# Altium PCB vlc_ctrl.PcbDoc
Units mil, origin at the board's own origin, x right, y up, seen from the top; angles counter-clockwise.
Board outline 1075 x 600 mil, 2 copper layers (Top Layer, Bottom Layer); 22 components, 13 nets, 59 pads, 2 vias.
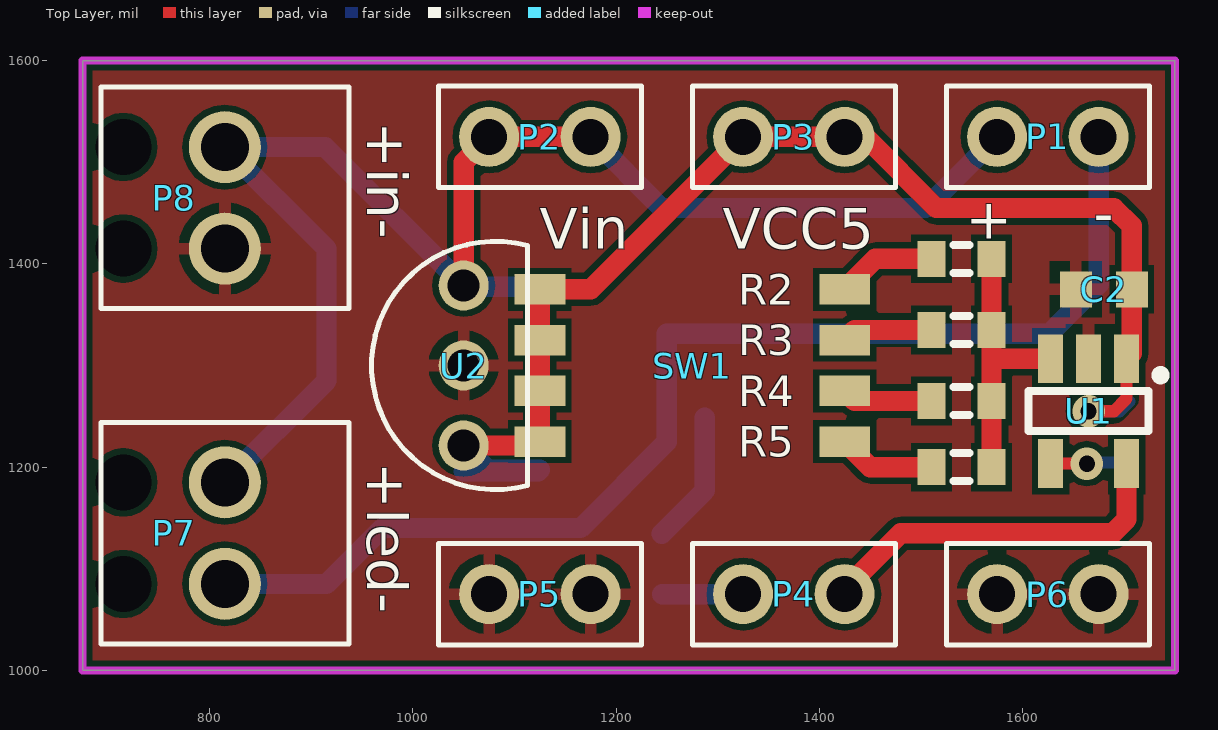
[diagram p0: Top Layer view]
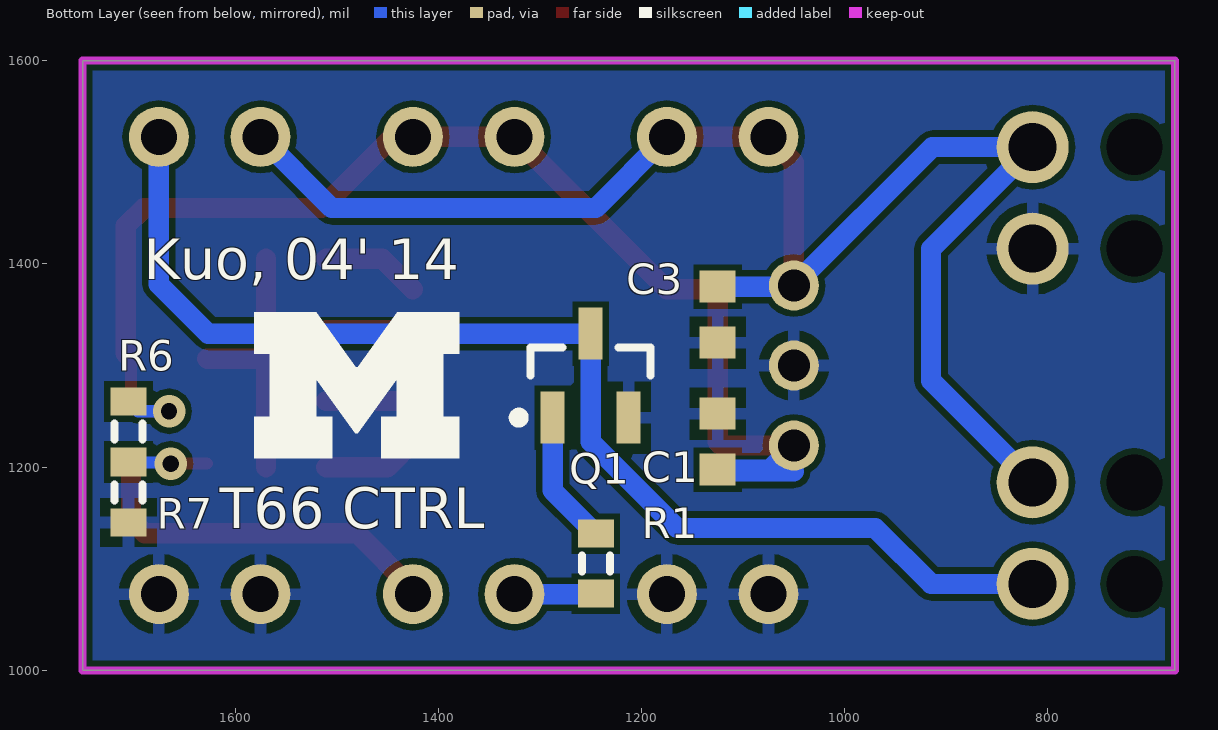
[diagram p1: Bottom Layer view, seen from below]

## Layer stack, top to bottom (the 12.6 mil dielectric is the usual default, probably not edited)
Top Solder: solder mask 0.4, Solder Resist, Dk 3.5
Top Layer: signal copper 1.4
Dielectric 1: dielectric 12.6, FR-4, Dk 4.8
Bottom Layer: signal copper 1.4
Bottom Solder: solder mask 0.4, Solder Resist, Dk 3.5

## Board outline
675,1000 675,1600 1750,1600 1750,1000

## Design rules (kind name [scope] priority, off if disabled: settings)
Clearance "Clearance~Sunstone Circuits" [All] p1: gap=6 // Sunstone Circuits Minimum Clearance Rule (Double Sided)
HoleSize "HoleSize~Sunstone Circuits" [All] p1: absolutevalues=TRUE maxlimit=251 minlimit=16 maxpercent=80.000 minpercent=20.000 // SSC Hole Size Rule For Single Sided & Double Sided Designs.
HoleSize Testpoint [All] p2: absolutevalues=TRUE maxlimit=100 minlimit=1 maxpercent=80.000 minpercent=20.000
HoleSize TestPointUsage [All] p3: absolutevalues=TRUE maxlimit=100 minlimit=1 maxpercent=80.000 minpercent=20.000
MinimumAnnularRing "MinimumAnnularRing~Sunstone Circuits" [All] p1: minimumring=7 // Sunstone Circuits Minimum Annular Ring (Double Sided)
PlaneClearance "PlaneClearance~Sunstone Circuits" [All] p1: clearance=12 // Sunstone Circuits Power Plane Clearance Rule (Double Sided)
PlaneConnect "PlaneConnect~Sunstone Circuits" [All] p1: planeconnectstyle=Relief reliefexpansion=10 reliefentries=4 reliefconductorwidth=8 reliefairgap=10 // Sunstone Circuits Power Plane Connect Rule (Double Sided)
PolygonConnect "PolygonConnect~Sunstone Circuits" [All] p1: connectstyle=Relief reliefconductorwidth=12 reliefentries=4 polygonreliefangle="90 Angle" airgapwidth=10 // Sunstone Circuits Polygon Connect Style (Double Sided)
RoomDefinition vlc_ctrl [InComponentClass('vlc_ctrl')] p1: confinementstyle=ConfineIn formatcopy=TRUE lockcomponents=FALSE outline 677.44,1013.44 677.44,1586.56 1012.5,1586.56 1012.5,1587.5 1737.5,1587.5 1737.5,1408.62 1739.21,1408.62 1739.21,1343.59 1754.8,1343.59 1754.8,1166.41 1737.5,1166.41 1737.5,1012.5 1012.5,1012.5 1012.5,1013.44
RoutingVias "RoutingVias~Sunstone Circuits" [All] p1: holewidth=16 width=30 viastyle="Through Hole" minholewidth=16 minwidth=30 maxholewidth=20 maxwidth=40 // Sunstone Circuits Routing Vias Rule (Double Sided)
ShortCircuit "ShortCircuit~Sunstone Circuits" [All] p1: allowed=FALSE // Sunstone Circuits Short Circuit Rule~Do Not Allow (Double Sided)
SolderMaskExpansion "SolderMaskExpansion~Sunstone Circuits" [All] p1: expansion=3 // Sunstone Circuits Solder Mask Expansion Rule (Double Sided)
ViasUnderSMD "ViasUnderSMD~Sunstone Circuits" [All] p1: allowed=FALSE // Sunstone Circuits Vias Under SMD~Do Not Allow (Double Sided)
Width "Width~Sunstone Circuits" [All] p1: maxlimit=100 minlimit=6 preferedwidth=10 // Sunstone Circuits Minimum Width Rule (Double Sided)
25 further rules are at their usual default settings.

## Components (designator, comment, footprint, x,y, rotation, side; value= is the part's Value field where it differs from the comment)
C1 "Cap Semi" 1608[0603] 1125,1225 r270 bottom
C2 "Cap Semi" 1608[0603] 1680,1375 r0 top
C3 "Cap Semi" 1608[0603] 1125,1350 r90 bottom
P1 "1 x 2 header" "1X2 HEADER" 1625,1525 r180 top
P2 "1 x 2 header" "1X2 HEADER" 1125,1525 r180 top
P3 "1 x 2 header" "1X2 HEADER" 1375,1525 r180 top
P4 "1 x 2 header" "1X2 HEADER" 1375,1075 r180 top
P5 "1 x 2 header" "1X2 HEADER" 1125,1075 r180 top
P6 "1 x 2 header" "1X2 HEADER" 1625,1075 r180 top
P7 "Screw connector" MPT_2POSITION 815,1135 r270 top
P8 "Screw connector" MPT_2POSITION 815,1465 r270 top
Q1 "Si2312CDS" SOT95P250-3N 1250,1290 r90 bottom
R1 "Res3" J1-0603 1245,1105 r270 bottom
R2 "Res3" J1-0603 1540,1405 r180 top
R3 "Res3" J1-0603 1540,1335 r180 top
R4 "Res3" J1-0603 1540,1265 r180 top
R5 "Res3" J1-0603 1540,1200 r180 top
R6 "Res3" J1-0603 1705,1235 r90 bottom
R7 "Res3" J1-0603 1705,1175 r270 bottom
SW1 "CHS-04TB" CHS04TB 1275,1300 r270 top
U1 "LTC6900" TSOT23 1665,1255 r180 top
U2 "LM78L05" TO92 1050,1300 r90 top

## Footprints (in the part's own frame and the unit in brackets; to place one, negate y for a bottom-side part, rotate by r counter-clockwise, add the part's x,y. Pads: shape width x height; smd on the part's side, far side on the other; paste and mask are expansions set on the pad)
"1X2 HEADER" [mm] "1x2 header, 100 mils"
  round 1.5 hole 0.9: 1(-1.27,0) 2(1.27,0)
  silkscreen extent -2.54,-1.27 2.54,1.27, body extent -2.53,-1.26 2.53,1.26, height 8.38
1608[0603] [mm] "Chip Capacitor, Body 1.6x0.8mm, IPC High Density"
  rect 0.8x0.9 smd: 1(-0.7,0) 2(0.7,0)
  body extent -0.87,-0.48 0.87,0.48, height 1.3
CHS04TB [mm] "4 POS DIP SWITCH"
  rect 0.76x1.27 smd: 1(-1.905,-3.81) 2(-1.905,3.81) 3(-0.635,-3.81) 4(-0.635,3.81) 5(0.635,-3.81) 6(0.635,3.81) 7(1.905,-3.81) 8(1.905,3.81)
J1-0603 [mm] "Chip Resistor, Body 1.6x0.8mm, IPC High Density"
  rect 0.7x0.9 smd: 1(-0.75,0) 2(0.75,0)
  silkscreen extent -0.2,-0.35 0.2,0.35, body extent -0.85,-0.48 0.85,0.48, height 0.9
MPT_2POSITION [mm] "Screw connector 2 pos"
  round 1.8 hole 1.2: 1(-1.27,0) 2(1.27,0)
  round 0 hole 1.4: ""(-1.27,-2.54) ""(1.27,-2.54)
  silkscreen extent -2.77,-3.1 2.77,3.1
SOT95P250-3N [mm] "SOT23, 3-Leads, Body 2.9x1.3mm, Pitch 0.95mm, Lead Span 2.3mm, IPC Medium Density"
  rect 1.3x0.6 smd: 1(-1.05,0.95) 2(-1.05,-0.95) 3(1.05,0)
  silkscreen extent -1.17,-1.5 0.7,1.93, body extent -0.7,-1.5 0.7,1.5, height 1.2
TO92 [mm]
  round 1.25 hole 0.8: 1(-2,0) 2(0,0) 3(2,0)
  silkscreen extent -3.1,-1.6 3.1,2.3
TSOT23 [mm]
  rect 0.62x1.22 smd: 1(-0.95,-1.31) 2(0,-1.31) 3(0.95,-1.31) 4(0.95,1.31) 5(-0.95,1.31)
  silkscreen extent -1.9,-1 1.5,0.5

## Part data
C1 C2 C3: "Capacitor (Semiconductor SIM Model)"
P1 P2 P3 P4 P5 P6: "100 mils standard header"
P7 P8: library part MPT_2POS, "Screw connector 2 positions"
Q1: "N-Channel 20 V (D-S) MOSFET"
R1 R2 R3 R4 R5 R6 R7: "Resistor"
SW1: "SLIDE SWITCHES"
U1: "Low Power, 1kHz to 20MHz   Resistor Set SOT-23 Oscillator"
U2: "LM78LXX Series 3-Terminal Positive Regulators"

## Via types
v1: diameter 32, hole 16, Top Layer to Bottom Layer, 2 vias

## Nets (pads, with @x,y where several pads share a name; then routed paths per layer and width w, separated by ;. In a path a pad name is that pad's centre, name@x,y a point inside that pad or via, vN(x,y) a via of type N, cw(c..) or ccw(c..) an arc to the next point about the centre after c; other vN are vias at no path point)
GND: C1.1 C2.1 C3.1 P5.1 P5.2 P6.1 P6.2 P8.2 Q1.2 R7.2 U1.2 U2.2
NetP1_1: P1.1 P7.2 Q1.3 | length 1189.5
  Bottom Layer w20: P7.2 915,1085 970,1140 1165,1140 1250,1225 Q1.3 1626.34,1331.34 1675,1380 P1.1
NetP4_1: P4.1 U1.5 | length 365.7
  Top Layer w20: P4.1 1425,1080 1480,1135 1688.83,1135 1702.4,1148.57 U1.5
NetP4_2: P4.2 R1.2 | length 79.5
  Bottom Layer w20: R1.2@1245.47,1075 P4.2
NetQ1_1: Q1.1 R1.1 | length 131.7
  Bottom Layer w20: R1.1 1287.4,1176.93 Q1.1
NetR2_1: R2.1 R3.1 R4.1 R5.1 U1.3 | length 261.5
  Top Layer w20: R5.1 R4.1 R3.1 R2.1 ; 1571.1,1306.57 U1.3
NetR2_2: R2.2 SW1.2 | length 97.9
  Top Layer w20: SW1.2 1455,1405 R2.2
NetR3_2: R3.2 SW1.4 | length 89.6
  Top Layer w20: SW1.4 1435,1335 R3.2
NetR4_2: R4.2 SW1.6 | length 89.6
  Top Layer w20: SW1.6 1435,1265 R4.2
NetR5_2: R5.2 SW1.8 | length 95.8
  Top Layer w20: SW1.8 1450,1200 R5.2
NetR6_1: R6.1 R7.1 U1.4 | length 77.9
  Top Layer w12: U1.4 v1(1663.43,1203.43)
  Bottom Layer w12: v1(1663.43,1203.43) 1664.53,1204.53 R7.1
VCC5: C1.2 C2.2 P3.1 P3.2 R6.2 SW1.1 SW1.3 SW1.5 SW1.7 U1.1 U2.1 | length 1324.3
  Top Layer w12: v1(1665,1255) 1690,1255 1702.4,1267.4 U1.1
  Top Layer w20: U2.1 1121.26,1221.26 SW1.7 SW1.5 SW1.3 SW1.1 1175,1375 P3.2 P3.1 1445,1525 1515,1455 1690,1455 1707.56,1437.44 C2.2 1707.56,1311.73 U1.1
  Bottom Layer w12: v1(1665,1255) 1695.47,1255 R6.2
  Bottom Layer w20: 1050,1195.67 C1.2@1123.23,1195.67 ; U2.1 1073.82,1197.44 C1.2
VIN: C3.2 P1.2 P2.1 P2.2 P7.1 P8.1 U2.3 | length 1494.4
  Top Layer w20: U2.3 1050,1500 P2.2 P2.1
  Bottom Layer w20: P7.1 915,1285 915,1415 P8.1 913.74,1515 U2.3 1051.18,1377.56 C3.2 ; P2.1 1245,1455 1505,1455 P1.2
pads on no net: P7. P8.

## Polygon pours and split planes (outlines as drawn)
GND on Top Layer "Bottom Layer-No Net" (solid, pour order 2): 675,1600 1750,1600 1750,1000 675,1000
GND on Bottom Layer "Bottom Layer-No Net" (solid, pour order 4): 675,1600 1750,1600 1750,1000 675,1000

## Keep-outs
Keep-Out Layer:
  the board outline again, w7.87

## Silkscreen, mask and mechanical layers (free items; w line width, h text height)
Top Overlay:
  text "+in-" at 955,1540 h40 r270
  text "-" at 1690,1430 h40
  text "+" at 1590,1425 h40
  text "Vin" at 1125,1415 h40
  text "VCC5" at 1305,1415 h40
  text "+led-" at 955,1205 h40 r270
Bottom Overlay:
  region: 1581.1,1208.63 1504.38,1208.63 1504.38,1249.6 1519.98,1249.6 1519.98,1286.66 1481.94,1233.34 1479.34,1233.34 1440.66,1286.66 1440.66,1249.6 1456.26,1249.6 1456.26,1208.63 1379.54,1208.63 1379.54,1249.6 1395.14,1249.6 1395.14,1311.37 1379.54,1311.37 1379.54,1352.33 1440.33,1352.33 1479.34,1298.36 1481.29,1298.36 1520.31,1352.33 1581.1,1352.33 1581.1,1311.37 1566.14,1311.37 1566.14,1249.6 1581.1,1249.6
  text "Kuo, 04' 14" at 1690,1385 h40
  text "T66 CTRL" at 1615,1140 h40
